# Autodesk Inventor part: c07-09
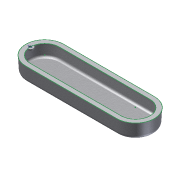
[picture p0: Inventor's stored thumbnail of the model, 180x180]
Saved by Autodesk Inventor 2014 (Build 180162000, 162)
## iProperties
Created: 2011-12
Part Number: c07-09
Material: Aluminum 6061-AHC
Document SubType Name: Modeling
Designer: Thom Tremblay
Density: 1 g/cm^3
Appearance: Aluminum Cast
Author: Thom Tremblay
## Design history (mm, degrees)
sketch "Sketch1"
  geometry: L1 (-76.2, -31.75)-(76.2, -31.75); L2 (76.2, -31.75)-(76.2, 31.75); L3 (76.2, 31.75)-(-76.2, 31.75); L4 (-76.2, 31.75)-(-76.2, -31.75); L5 (-76.2, -31.75)-(76.2, 31.75); L6 (76.2, -31.75)-(-76.2, 31.75); 3 further points
  constraints: 12 end point, 4 midpoint, 2 parallel, 2 vertical alignment, 1 horizontal, 1 perpendicular, 4 other
  dimensions: "d0" = 152.4 distance of L3.end L2.end; "d1" = 63.5 distance of L2.end L1.end
extrude "Extrusion1" new body sketch "Sketch1" distance "d2" = 25.4; taper "d3" = 0 deg
feature "FaceDraft1" dims angle "d20" = 3 deg
fillet "Fillet1" dims "d4" = 6.35
sketch "Sketch2"
  geometry: L1 (-76.2, -31.75)-(76.2, -31.75) reference; L2 (76.2, 31.75)-(-76.2, 31.75) reference; L3 (-76.2, 24.13)-(76.2, 24.13); L4 (76.2, -24.13)-(-76.2, -24.13); A1 r 31.75 centre (76.2, 0) between (76.2, -31.75) and (76.2, 31.75) reference; A2 r 31.75 centre (-76.2, 0) between (-76.2, 31.75) and (-76.2, -31.75) reference; A3 r 24.13 centre (76.2, 0) between (76.2, -24.13) and (76.2, 24.13); A4 r 24.13 centre (-76.2, 0) between (-76.2, 24.13) and (-76.2, -24.13); 1 further point
  constraints: 4 end point, 4 point on circle, 2 centre point, 3 other
  dimensions: "d5" = 7.62 radial gap between concentric circles of A2 A4
split "Split1" sketch "Sketch2"
shell "Shell1" dims "d7" = 2.54
sketch "Sketch4"
  geometry: L1 (0, 0)-(152.4, 0) reference; L2 (152.4, 63.5)-(0, 63.5) reference; L3 (0, 7.62)-(152.4, 7.62) reference; L4 (152.4, 55.88)-(0, 55.88) reference; A1 r 31.75 centre (152.4, 31.75) between (152.4, 0) and (152.4, 63.5) reference; A2 r 31.75 centre (0, 31.75) between (0, 63.5) and (0, 0) reference; A3 r 24.13 centre (152.4, 31.75) between (152.4, 7.62) and (152.4, 55.88) reference; A4 r 24.13 centre (0, 31.75) between (0, 55.88) and (0, 7.62) reference; 1 further point
  constraints: 1 point on circle
sketch "Sketch3"
  geometry: C1 r 5.08 at (-24.13, 31.75); A1 r 24.13 centre (0, 31.75) between (0, 55.88) and (0, 7.62) reference; 1 further point
  constraints: 1 centre point, 1 point on circle
  dimensions: "d8" = 10.16 diameter of C1
extrude "Hole Boss" join sketch "Sketch3" distance "d9" = 2.54; taper "d10" = 0 deg
hole "Hole1" diameter "d13" = 4.3434; stored, may be unused: countersink angle "d17" = 82 deg, drill point angle "d19" = 118 deg; dims "d11" = 25.4, "d12" = 25.4, "d14" = 19.05, "d15" = 9.525, "d16" = 6.35, "d18" = 2.54
body "Solid1"
